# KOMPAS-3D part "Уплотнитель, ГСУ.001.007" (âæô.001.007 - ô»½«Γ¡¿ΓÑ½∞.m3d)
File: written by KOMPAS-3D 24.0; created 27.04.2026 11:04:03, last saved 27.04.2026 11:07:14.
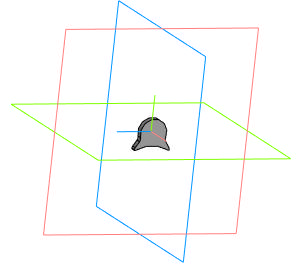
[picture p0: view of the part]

Document properties: Автор: User7; Полное имя файла: C:\Users\User7\Desktop\Двигатель мясорубки\ГСУ.001.007 - Уплотнитель.m3d

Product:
- Part/product: Уплотнитель  | designation ГСУ.001.007
    Масса: 0.000505

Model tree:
1. Эскиз:1
2. Элемент выдавливания:1
     Расстояние 1 = 1.5
3. Эскиз:2  (with: Грань.Элемент выдавливания:1, Ребро.Элемент выдавливания:1)
4. Эскиз:3  (with: Грань.Элемент выдавливания:1)
5. Элемент выдавливания:2
6. Элемент выдавливания:3

Expressions: 7.7*2
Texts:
  ГСУ.001.007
